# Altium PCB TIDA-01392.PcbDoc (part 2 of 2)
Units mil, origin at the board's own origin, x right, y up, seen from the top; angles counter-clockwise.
Board outline 1055.12 x 1877.5 mil, 6 copper layers (Layer 1 - Top Layer, Layer 2 - GND, Layer 3 - Signal, Layer 4 - Signal, Layer 5 - PWR, Layer 6 - Bottom Layer), stack 66.234 mil thick; 89 components, 55 nets, 288 pads, 112 vias.
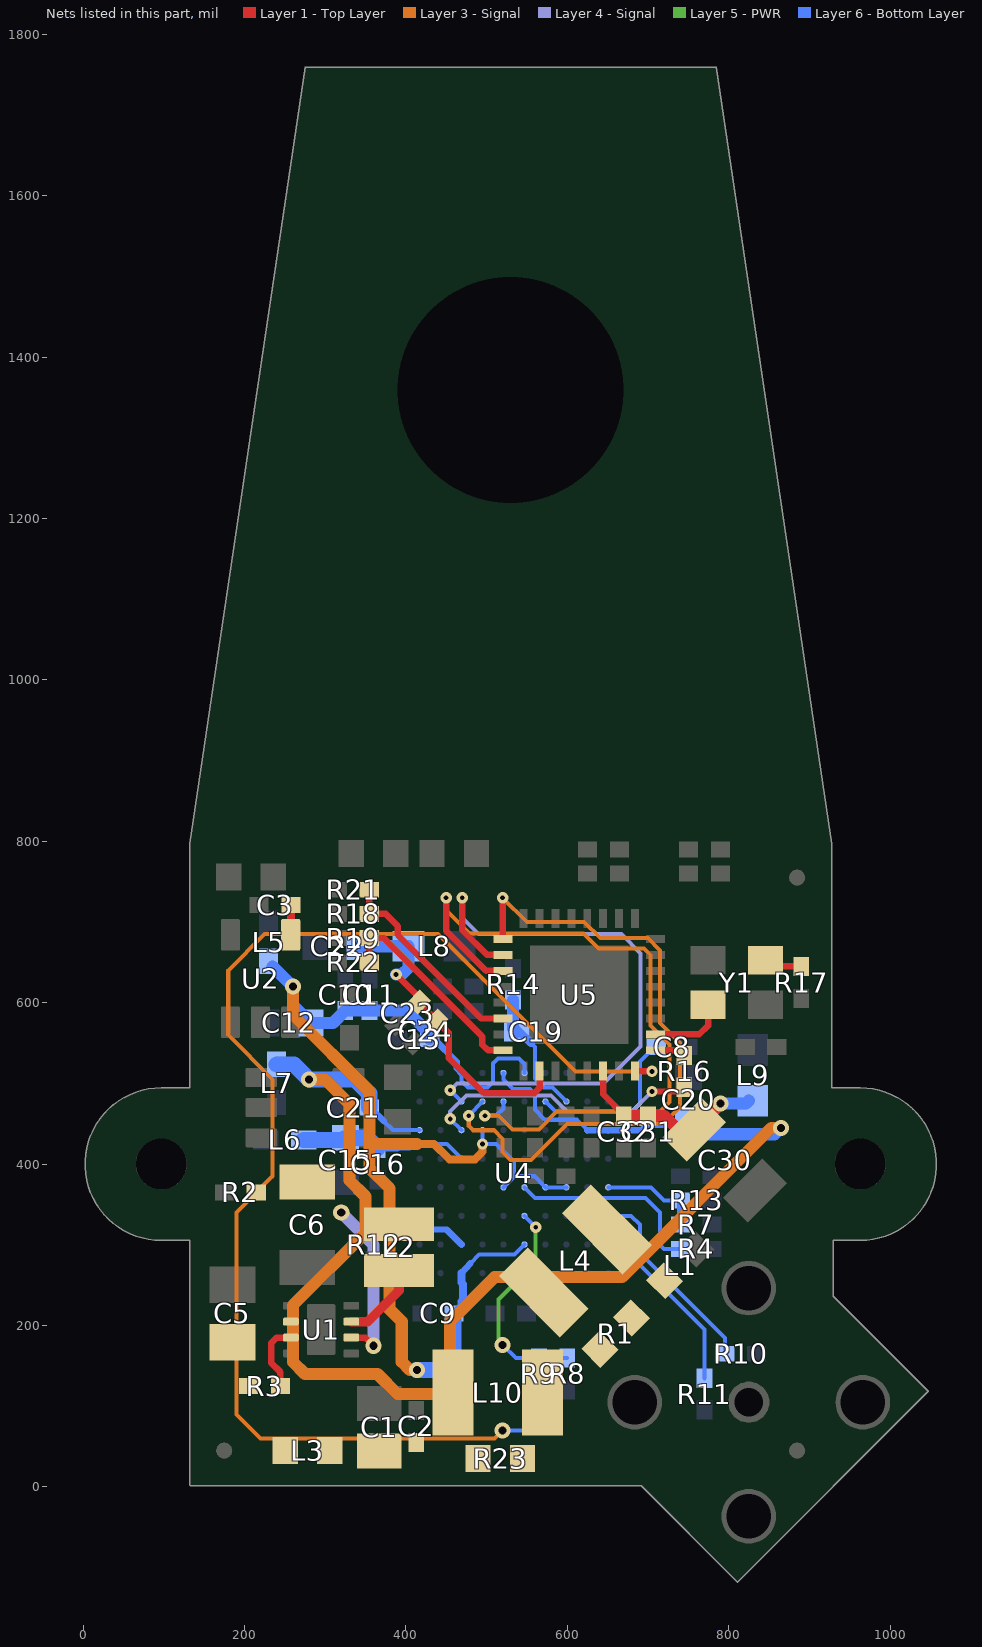
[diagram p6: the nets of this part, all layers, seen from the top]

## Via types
v1: diameter 20, hole 10, Layer 1 - Top Layer to Layer 6 - Bottom Layer, tented both sides, 57 vias
v2: diameter 14, hole 6, Layer 1 - Top Layer to Layer 6 - Bottom Layer, tented both sides, 46 vias
v3: diameter 19.68, hole 7.87, Layer 1 - Top Layer to Layer 6 - Bottom Layer, tented both sides, 7 vias
v4: diameter 20, hole 10, Layer 1 - Top Layer to Layer 6 - Bottom Layer, 2 vias

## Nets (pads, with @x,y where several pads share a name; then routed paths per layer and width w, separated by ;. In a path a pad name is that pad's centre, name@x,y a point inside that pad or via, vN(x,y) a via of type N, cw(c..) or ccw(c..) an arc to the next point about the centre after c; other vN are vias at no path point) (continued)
HSYNC: U4.B7 U5.1 | length 831.3
  Layer 1 - Top Layer w8: v2(520,730) 520,679.41 U5.1@520.51,678.9
  Layer 3 - Signal w5: v2(478,460) 478,447 483,442 509,442 520,431 520,415 530,405 555,405 600,450 719,450 740,471 740,550 715,575 715,665 700,680 641,680 621,700 550,700 v2(520,730)
  Layer 6 - Bottom Layer w5: v2(478,460) 478,460.56 U4.B7@495.02,477.58
NetC1_1: C1.1 C2.1 L3.1 L10.2 R23.1
NetC3_1: C3.1 U2.4 | length 37.4
  Layer 1 - Top Layer w10: U2.4@257.4,684.13 257.68,684.42 C3.1@257.68,719 ; C3.1@257.4,718.72 C3.1@257.68,719 ; C3.1@257.68,721 C3.1@257.68,719
NetC6_1: C6.1 L2.2 R2.2 U1.6 | length 213.6
  Layer 1 - Top Layer w8: U1.6@332.56,185 U1.6@332.4,185.16 349.84,185.16 v1(360,175)
  Layer 4 - Signal w15: v1(320,340) 360,300 v1(360,175)
NetC8_1: C8.1 U4.B4 | length 206.1
  Layer 6 - Bottom Layer w5: U4.B4@572.98,477.58 585.56,465 680,465 690,475 690,527 708,545 C8.1@710.32,545
NetC9_1: C9.1 C10.1 C11.1 C12.1 C13.1 L5.2 U4.A5 U4.A8 U4.C7 U4.E3 U4.E4 U4.E6 U4.G5 U4.H8 | length 1592.5
  Layer 3 - Signal w10: 414,425 435,425 454,406 485.57,406 495,415.43 v2(495,425)
  Layer 3 - Signal w15: v1(260,620) 260,585 355,490 355,425 ; v1(414,145) 405,145 395,155 395,205 380,220 380,370 355,395 355,425 ; 414,425 355,425
  Layer 6 - Bottom Layer w5: U4.A8@469.04,513.02 469.04,502.96 477,495 501,495 508,502 508,525 514,531 540,531 546.99,524.01 U4.A5@546.99,513.02 ; 480,277 491,288 534.57,288 U4.G5@546.99,300.42 ; U4.C7@495.02,442.15 v2@495.02,428 ; U4.E6@521.01,371.28 534,384.28 534,403 512,425 v2(495,425) ; 534.72,385 559.26,385 U4.E4@572.98,371.28 U4.E3@598.96,371.28 ; v2(495,425) v2@495,427.98 ; v2(495,425) v2@495.02,428
  Layer 6 - Bottom Layer w8: C13.1@429.68,555 435,555 463.04,526.96 463.04,519.02 U4.A8@469.04,513.02 ; U4.H8@469.04,264.98 480,277
  Layer 6 - Bottom Layer w10: C9.1@462,215 C9.1@459.68,215 469.04,224.35 469.04,229.9 471,231.86 471,251.14 469.04,253.1 U4.H8@469.04,264.98
  Layer 6 - Bottom Layer w15: L5.2@235,645 v1(260,620) 260,597.56 C12.1@282.56,575 309.68,575 C10.1@325,590.32 C11.1@355,590.32 400.68,590.32 432.84,558.16 C13.1@429.68,555
  Layer 6 - Bottom Layer w20: v1(414,145) 435,145 459,155 C9.1@459,210
NetC15_1: C15.1 C16.1 L6.2 U4.D8 | length 211.6
  Layer 6 - Bottom Layer w5: 389.68,419.68 404.68,419.68 410,425 450.76,425 U4.D8@469.04,406.72
  Layer 6 - Bottom Layer w8: C16.1@365,419.68 389.68,419.68
  Layer 6 - Bottom Layer w20: L6.2@273.62,430 322.44,430 C15.1@325,432.56 352.13,432.56 C16.1@365,419.68
NetC19_1: C19.1 R14.1 U4.B3 | length 161.4
  Layer 6 - Bottom Layer w5: 555,550 560,545 560,506 571,495 581.54,495 U4.B3@598.96,477.58
  Layer 6 - Bottom Layer w10: C19.1@537.38,564 541,564 555,550
  Layer 6 - Bottom Layer w15: R14.1@533,603.32 533,568.38 C19.1@537.38,564
NetC20_1: C20.1 C21.1 L7.2 U4.A6 U4.C1 U4.C2 U4.C10 | length 1852.9
  Layer 3 - Signal w15: v1(280,505) 300,505 330,475 330,380 350,360 350,315 260,225 260,155 275,140 365,140 390,115 440,115 455,130 455,205 510,260 668,260 853,445 v1(865,445)
  Layer 6 - Bottom Layer w5: 373,453 383.85,442.15 U4.C10@417.07,442.15 ; U4.A6@521.01,513.02 521.01,504.99 533,493 554,493 560,487 560,467.65 572.65,455 612.09,455 U4.C2@624.94,442.15
  Layer 6 - Bottom Layer w8: C21.1@354.68,470 356,470 373,453 ; U4.C2@624.94,442.15 U4.C1@650.93,442.15 692.15,442.15 698.5,448.5 C20.1@750,448.5
  Layer 6 - Bottom Layer w15: C20.1@750,452.44 765.44,437 857,437 v1(865,445)
  Layer 6 - Bottom Layer w20: L7.2@240,523.62 261.38,523.62 v1(280,505) 337,505 354.68,487.32 C21.1@354.68,470
NetC22_1: C22.1 C23.1 C24.1 L8.2 U5.10 | length 390.9
  Layer 1 - Top Layer w8: v2(388,635) 415.92,607.08 C23.1@415.92,600.92 415.92,599.92 C24.1@437.92,577.92 453,562.84 453,532 497,488 559,488 565.79,494.79 U5.10@565.79,515.51
  Layer 6 - Bottom Layer w15: C22.1@342.56,670 L8.2@403.5,670 403.5,643.5 395,635 v2(388,635)
NetC30_1: C30.1 C31.1 C32.1 L9.2 U5.14 | length 243.3
  Layer 1 - Top Layer w8: U5.14@644.53,515.51 644.53,486.47 670,461 C32.1@670,459.68
  Layer 1 - Top Layer w15: C32.1@670,459.68 C31.1@700,459.68 720.32,459.68 737.42,442.58 C30.1@757.42,442.58 v1(789.84,475)
  Layer 6 - Bottom Layer w15: v1(789.84,475) 821.5,475 L9.2@825,478.5
NetL1_1: L1.1 L4.1 R1.2
NetL2_1: L2.1 U1.7 | length 100.1
  Layer 1 - Top Layer w12: U1.7@332.4,204.84 352.84,204.84 391.5,243.5 L2.1@391.5,268.46
NetL4_2: L4.2 L10.1 R1.1 R23.2
NetR3_1: R3.1 U1.3 | length 85.4
  Layer 1 - Top Layer w8: R3.1@244.68,125 244.68,142.32 233,154 233,178 240.16,185.16 U1.3@257.6,185.16
NetR4_1: R4.1 U4.E5 | length 248.4
  Layer 6 - Bottom Layer w5: U4.E5@546.99,371.28 560.28,358 697,358 715,340 715,300 720,295 R4.1@740.32,295
NetR7_1: R7.1 R13.2 U4.E1 | length 126.1
  Layer 6 - Bottom Layer w5: U4.E1@650.93,371.28 703.72,371.28 720,355 R13.2@740.31,355
  Layer 6 - Bottom Layer w8: R7.1@740.32,325 R13.2@740.31,355
NetR8_1: R8.1 R9.1 U4.F5 | length 272.6
  Layer 5 - PWR w5: v1(520,176) 515,185 515,232.02 560.98,278 v2(560.98,321.86)
  Layer 6 - Bottom Layer w5: v1(520,176) 536.68,159.68 R9.1@565,159.68 R8.1@600,159.68 ; U4.F5@546.99,335.85 v2(560.98,321.86)
NetR10_2: R10.2 U4.F1 | length 247.2
  Layer 6 - Bottom Layer w5: U4.F1@650.93,335.85 679.15,335.85 690,325 690,290 795.31,184.69 R10.2@795.31,165
NetR11_2: R11.2 U4.F2 | length 281.3
  Layer 6 - Bottom Layer w5: U4.F2@624.94,335.85 636.8,324 671,324 680,315 680,285 770,195 R11.2@770,134.69
NetR12_2: R12.2 U4.G8 | length 117
  Layer 6 - Bottom Layer w8: R12.2@360,319.69 360.69,319 450.46,319 U4.G8@469.04,300.42
NetR16_1: R16.1 U5.17 | length 38.2
  Layer 1 - Top Layer w8: U5.17@709.49,541.1 738.58,541.1 R16.1@745,534.68
NetR17_1: R17.1 Y1.1 | length 47.8
  Layer 1 - Top Layer w8: Y1.1@845.43,652.56 852.99,645 889.68,645 R17.1@890,644.68
NetR18_1: R18.1 R21.2 U5.6 | length 255.9
  Layer 1 - Top Layer w8: R21.2@354.69,740 R18.1@354.68,710 375,710 390,695 390,684 493.53,580.47 U5.6@520.51,580.47
NetR19_1: R19.1 R22.2 U5.8 | length 259.2
  Layer 1 - Top Layer w8: R22.2@354.69,650 R19.1@354.68,680 373,680 494.9,558.1 494.9,548.1 501.9,541.1 U5.8@520.51,541.1
NetU5_18: U5.18 Y1.3 | length 95.4
  Layer 1 - Top Layer w8: U5.18@709.49,560.79 763.79,560.79 774.57,571.57 Y1.3@774.57,597.44
NRST: R9.2 U5.16 | length 1662.8
  Layer 1 - Top Layer w8: U5.16@683.9,515.51 684.41,515 v2(705,515)
  Layer 3 - Signal w5: v1(520,70) 510,60 220,60 190,90 190,340 235,385 235,505 180,560 180,640 225,685 440,685 610,515 v2(705,515)
  Layer 6 - Bottom Layer w5: v1(520,70) 536,70 555,70 565,80 R9.2@565,120.31
PCLK: U4.B6 U5.3 | length 900.6
  Layer 1 - Top Layer w8: v2(450,730) 450,689 499.47,639.53 U5.3@520.51,639.53
  Layer 3 - Signal w5: v2(450,730) 450,715 479,686 620,686 639,667 695,667 703,659 703,572 727,548 727,477 715,465 587,465 565,443 532,443 515,460 v2(498,460)
  Layer 6 - Bottom Layer w5: v2(498,460) 512,460 521.01,469.01 U4.B6@521.01,477.58
VCC_POC: C5.1 L3.2 R3.2 U1.2
VSYNC: U4.B8 U5.2 | length 760.8
  Layer 1 - Top Layer w8: v2(470,730) 470,690 500.79,659.21 U5.2@520.51,659.21
  Layer 4 - Signal w5: v2(455.05,491.57) 463.47,500 645,500 691,546 691,661 667,685 490,685 470,705 v2(470,730)
  Layer 6 - Bottom Layer w5: v2(455.05,491.57) U4.B8@469.04,477.58
XCLK: R16.2 U4.C8 | length 347.8
  Layer 1 - Top Layer w8: v2(705,490) 739.69,490 R16.2@745,495.31
  Layer 4 - Signal w5: v2(455.05,456.14) 455.05,465.05 475,485 580,485 600,465 680,465 v2(705,490)
  Layer 6 - Bottom Layer w5: v2(455.05,456.14) U4.C8@469.04,442.15
pads on no net: FID1.1 FID2.1 FID3.1 FID4.1 FID5.1 FID6.1 LH1.MT1 LH1.MT2 U3.4 U4.C5

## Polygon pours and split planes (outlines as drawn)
1V8 on Layer 5 - PWR "Layer 5 - PWR- 1V8" (solid, remove dead copper, pour order 2): 295,792 605.5,792 613.5,784 613.5,758.5 605,750 511,750 502,741 502,722 512.97,711.03 676.03,711.03 712,747 712,787 717,792 744,792 801,735 898,735 898,408 830,340 830,305 820,295 785,295 624.75,134.75 624.75,49.75 606,31 163,31 163,389 199,425 199,484 163,520 163,759.5 262.5,759.5
GND on Layer 2 - GND "Layer 2 - GND- GND" (solid, remove dead copper, pour order 4): 0,-120 1060,-120 1060,802 0,802

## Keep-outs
Keep-Out Layer:
  lines w10: 96.88,300.51 ccw(c96.93,400) 96.93,300.51 ; 96.88,300.51 cw(c96.93,400) 96.88,499.49 ; 96.88,300.51 ccw(c96.93,305.51) 96.93,300.51 ; 96.88,499.49 cw(c96.93,494.49) 96.93,499.49 ; 96.88,499.49 cw(c96.93,494.49) 96.93,499.49 ; 96.88,499.49 cw(c96.93,400) 96.93,499.49 ; 96.93,300.51 127.36,300.51 127.36,2.36 ; 96.93,499.49 127.36,499.49 127.36,796.93 ; 127.36,2.36 ccw(c132.36,2.36) 128.84,-1.19 ; 127.36,2.36 ccw(c132.36,2.36) 128.83,-1.17 128.84,-1.19 ; 127.36,796.93 cw(c132.36,797) 127.36,797 ; 127.36,796.93 cw(c132.36,797) 127.36,797 ; 127.36,796.93 127.36,797.07 ; 127.36,797 cw(c132.36,797) 127.36,797.07 ; 127.36,797 127.36,797.64 ; 127.36,797.07 127.36,797.64 ; 127.36,797.64 cw(c132.36,797.64) 127.65,799.31 ; 127.36,797.64 ccw(c132.36,797.64) 127.36,797.64 ; 127.36,797.64 cw(c132.36,797.64) 127.65,799.31 ; 127.65,799.31 270.3,1760.23 ; 128.84,-1.19 129.8,-2.15 ; 129.82,-2.17 ccw(c133.35,1.37) 133.35,-3.63 ; 129.8,-2.15 ccw(c133.35,1.37) 133.35,-3.63 ; 129.8,-2.15 129.82,-2.17 ; 133.35,-3.63 689.56,-3.63 807.45,-121.52 ; 270.3,1760.23 cw(c275.25,1759.5) 275.25,1764.5 ; 270.3,1760.23 cw(c275.25,1759.5) 275.25,1764.5 ; 275.25,1764.5 784.75,1764.5 ; 784.75,1764.5 cw(c784.75,1759.5) 789.7,1760.23 ; 784.75,1764.5 cw(c784.75,1759.5) 789.7,1760.23 ; 789.7,1760.23 932.35,799.31 ; 807.45,-121.52 ccw(c811,-118) 814.54,-121.54 814.55,-121.52 ; 807.45,-121.52 807.46,-121.54 ccw(c811,-118) 814.55,-121.52 ; 814.55,-121.52 1051.02,114.95 ; 932.35,799.31 cw(c927.64,797.64) 932.64,797.64 ; 932.35,799.31 cw(c927.64,797.64) 932.64,797.64 ; 932.64,796.91 ccw(c927.64,797) 932.64,797 ; 932.64,796.91 ccw(c927.64,797) 932.64,797 ; 932.64,796.91 932.64,797.09 ; 932.64,796.91 932.64,499.49 963.07,499.49 ; 932.64,797.01 ccw(c927.64,797) 932.64,797.09 ; 932.64,797 ccw(c927.64,797) 932.64,797.01 ; 932.64,797 ccw(c927.64,797) 932.64,797.01 ; 932.64,797.01 932.64,797.64 ; 932.64,797.09 932.64,797.64 ; 932.64,797.64 ccw(c927.64,797.64) 932.64,797.64 ; 963.07,300.51 ccw(c963.07,400) 963.12,300.51 ; 963.07,300.51 ccw(c963.07,305.51) 963.12,300.51 ; 963.07,300.51 ccw(c963.07,305.51) 963.12,300.51 ; 963.07,300.51 ccw(c963.07,305.51) 963.07,300.51 ; 963.07,300.51 934.63,300.51 934.63,238.44 1051.02,122.05 ; 963.07,499.49 cw(c963.07,494.49) 963.12,499.49 ; 963.07,499.49 cw(c963.07,400) 963.12,499.49 ; 963.07,499.49 ccw(c963.07,494.49) 963.07,499.49 ; 963.07,499.49 cw(c963.07,494.49) 963.12,499.49 ; 963.12,300.51 ccw(c963.07,400) 1062.56,400 ccw(c963.07,400) 963.12,499.49 ; 1051.02,114.95 ccw(c1047.5,118.5) 1052.5,118.5 ; 1051.02,114.95 1051.04,114.96 ccw(c1047.5,118.5) 1052.5,118.5 ; 1051.02,122.05 cw(c1047.5,118.5) 1052.5,118.5 ; 1051.02,122.05 1051.04,122.04 cw(c1047.5,118.5) 1052.5,118.5
  text ".Layer_Name" at 577,-858.49 h60

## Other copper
Layer 1 - Top Layer:
  region net NetL4_2: 551,297 627,221 627,208 664,171 640,147 595,102 595,64 560,29 560,17 530,17 529,18 529,53 542,66 542,171 552,171 576.75,195.75 513.25,259.25
  region net NetC1_1: 288,65 290,67 425,67 433,75 433,172 485,172 486,171 485,170 485,63.32 495.32,53 506,53 506,19 507,18 506,17 288,17
  region net 1V8: 309,491 407,491 407,523 355,575 309,575
  region net 1V5: 160,660 160,795 205,795 205,746 195,731 195,712 195,681 195,660
  region net GND: 550,419 550,433 570,433 570,419
  region net GND: 790,360 825,325 865,325 895,355 840,410
  region net 3V3: 188,355 188,398 210,420 241,420 241,445 195,445 190,450 190,490 195,495 241,495 270,524 270,596 245,596 245,550 240,545 200,545 195,550 195,596 160,596 160,355
  region net DOUT_N: 590,419 590,433 610,433 610,419
  region net DOUT_P: 620,419 620,433 640,433 640,419
  region net GND: 660,433 710,433 710,405 690,385 680,385 660,405
  region net 1V8: 820,620 900,620 900,542 893,535 865,535 845,535 845,555 820,580
  region net 1V8: 763,750 753,740 747,740 737,750 715,750 715,800 763,800
  region net GND: 777,750 825,750 825,800 777,800
  region net GND: 652,750 700,750 700,800 652,800
  region net 1V8: 638,750 628,740 622,740 612,750 590,750 590,800 638,800
  region net NetC6_1: 435,297 348,297 310,335 200,335 200,390 210,400 326,400 364,362 435,362
  region net GND: 425,125.5 425,81 293,81 270,104 270,138 247,161 247,171 270,171 277,178 277,212 270,219 155,219 155,320.5 294.5,320.5 313,302 313,133 320.5,125.5 335,125.5 350,125.5 375,125.5 400.5,125.5 415.5,125.5 420.5,125.5
  region net VCC_POC: 268,22 268,82 245,105 225,105 218,112 218,191 227,200 268,200 268,210 155,210 155,120 215,60 215,40 233,22
  region net NetL1_1: 643.5,361.5 745,260 745,251 680,186 654.5,211.5 638.18,291.18 606.25,324.25
  text ".Layer_Name" at 577,-858.49 h60
Layer 2 - GND:
  pour cut-out: 912.25,521.63 867.61,521.63 867.61,595.39 912.25,595.39
  pour cut-out: 459.08,297.08 459.08,325 437.71,325 437.71,370 385.75,370 385.75,415 437.71,415 437.71,508.91 480,508.91 480,479.33 558.33,479.33 558.33,444.67 517,444.67 517,409 532.33,409 532.33,367.18 552.33,367.18 552.33,297.08
  pour cut-out: 147.75,764.7 229.7,764.7 230,765 230,802 277,802 277,761 323,761 323,810 156,810 147.75,801.75
  pour cut-out: 502,712 502,803 677,803 680,800 680,712
  pour cut-out: 702,804 702,739 749,739 749,804
  text ".Layer_Name" at 577,-858.49 h60
Layer 5 - PWR:
  pour cut-out: 484,295 439,340 439,366 430,375 395,375 385,385 385,402 411,428 411,536 420,545 436,545 447,534 447,525 494,478 512,478 559,431 559,313 541,295
  text ".Layer_Name" at 577,-858.49 h60
Layer 3 - Signal:
  text ".Layer_Name" at 577,-858.49 h60
Layer 4 - Signal:
  text ".Layer_Name" at 577,-858.49 h60
Layer 6 - Bottom Layer:
  region net GND: 447,438 437,438 378,497 378,535 378,565 403,565 403,543 411,535 434,535 447,522 447,511 438,502 438,489 447,480 447,475 438,466 438,453 447,444
  region net GND: 613,473 655,473 655,515 675,535 675,670 555,670 554,669 554,590 569,575 569,510 572,507 590,507 613,484
  region net GND: 421,331 421,373 417,377 390,377 385,382 385,390 380,395 250,395 220,365 220,299 294,299 300,305 300,353 308,361 333,361 349,345 372,345 386,331
  region net 1V8: 767,335 810,335 825,320 825,300 810,285 767,285
  region net GND: 621,305 653,305 657,301 657,263 725,195 725,80 710,65 665,65 645,85 645,226 626,245 602,245 595,252 595,279
  region net GND: 565,269 577,269 577,255 565,243 565,195 550,180 540,180 535,185 535,260 544,269
  region net GND: 445,305 458.5,291.5 458.5,249.5 461,243 460,236.37 457,232 453,230 450,230 445,230 437,229 432,224 432,221.86 432,205 399.07,205 399.07,296.07 408,305
  text ".Layer_Name" at 577,-858.49 h60

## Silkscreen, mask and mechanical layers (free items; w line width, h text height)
Top Overlay:
  lines w7: 380,750 425,750 ; 520,385 520,395 ; 790,480 825,480
  text ".Layer_Name" at 577,-858.49 h60
Bottom Overlay:
  lines w10: 195,65 865,65 865,735 195,735 195,65
  text "TIDA-01392" at 205,1191 h70 r180
  text "ADAS-CAM-EVM-01392" at 179,906 h70 r180
  text ".Layer_Name" at 577,-858.49 h60
Top Paste:
  text ".Layer_Name" at 577,-858.49 h60
Bottom Paste:
  text ".Layer_Name" at 577,-858.49 h60
Top Solder:
  text ".Layer_Name" at 577,-858.49 h60
  text ".Layer_Name" at 577,-858.49 h60
Bottom Solder:
  text ".Layer_Name" at 577,-858.49 h60
Drill Guide:
  text ".Layer_Name" at 577,-858.49 h60
M1 Board Outline:
  lines w10: 132.36,2.36 132.36,305.51 96.93,305.51 cw(c96.93,400) 96.93,494.49 132.36,494.49 132.36,797.64 ; 132.36,797 275.25,1759.5 784.75,1759.5 927.64,797 ; 133.35,1.37 691.63,1.37 811,-118 1047.5,118.5 929.63,236.37 929.63,305.51 963.07,305.51 ccw(c963.07,400) 963.07,494.49 927.64,494.49 927.64,797.64 ; 137,822 164,822 ; 196,822 227.64,822 ; 259.64,822 291.28,822 ; 323.28,822 354.91,822 ; 386.91,822 418.55,822 ; 450.55,822 482.19,822 ; 514.19,822 545.83,822 ; 520,783 537,783 ; 530,735 530,775 ; 577.83,822 609.46,822 ; 641.46,822 673.1,822 ; 705.1,822 736.74,822 ; 768.74,822 800.38,822 ; 832.38,822 864.02,822 ; 896.02,822 922.97,822 ; 510,775 530,795 550,775 510,775
  text "V-SCORE" at 370,666 h75
  text ".Layer_Name" at 577,-858.49 h60
M2 Board Dimensions:
  rectangle: -0.5,-285.5 124.5,-160.5
  rectangle: 124.5,-410.5 499.5,-285.5
  lines w7: -0.5,-285.5 999.5,-285.5 ; 124.5,-410.5 124.5,-160.5 ; 249.5,-410.5 249.5,-160.5 ; 499.5,-410.5 499.5,-160.5 ; 749.5,-410.5 749.5,-160.5 ; -0.5,-410.5 999.5,-410.5 999.5,-160.5 -0.5,-160.5 -0.5,-410.5
  lines w10: -40,400 530,400 ; -0.5,-475.5 -0.5,-455.5 ; 59.5,-485.5 -0.5,-465.5 ; 59.5,-445.5 -0.5,-465.5 ; 223.58,-465.5 -0.5,-465.5 ; 530,-170 530,400 ; 530,970 530,400 ; 775.42,-465.5 999.5,-465.5 ; 939.5,-485.5 999.5,-465.5 ; 939.5,-445.5 999.5,-465.5 ; 999.5,-475.5 999.5,-455.5 ; 1100,400 530,400
  text "1000 (mil)" at 233.58,-501.49 h60
  text ".Layer_Name" at 577,-858.49 h60
M3 3D STEP Top:
  text ".Layer_Name" at 577,-858.49 h60
M4 3D STEP Bottom:
  text ".Layer_Name" at 577,-858.49 h60
M5 Assembly Top:
  lines w10: -292,-930.17 6308,-930.17 ; -292,-726.83 6310,-726.83 ; -292,-523.5 -292,-1133.5 3713,-1133.5 6310,-1133.5 6310,-523.5 -291.5,-523.5 -291.5,-1133.5 1284,-1133.5 ; 2173,-1133.5 2173,-523.5 ; 3440,-726.83 3440,-523.5 ; 4280,-726.83 4280,-523.5 ; 4902,-1140 4902,-937.17
  text "COMPONENTS MARKED 'DNP' SHOULD NOT BE POPULATED." at 1153.5,-318.5 h60
  text "ASSEMBLY VARIANT:" at 1153,-434 h60
  text ".VariantName" at 2189,-434 h60
  text "PCB VIEWED FROM TOP SIDE" at -228.5,-655.67 h60
  text "BOARD #:" at 2248,-655.67 h60
  text ".PRJ_Number" at 2793.5,-655.67 h60
  text "REV:" at 3638,-655.67 h60
  text ".PCB_Rev" at 3929.5,-655.67 h60
  text "SVN REV:" at 4476,-655.67 h60
  text ".VersionControl_RevNumber" at 4982,-655.67 h60
  text "IGNORE ->" at -228.5,-858.49 h60
  text "PLOT NAME =" at -228.5,-1064.34 h60
  text ".plot_File_Name" at 577,-1064.34 h60
  text "GENERATED    :" at 2250,-1064.34 h60
  text ".Print_Date" at 3119.5,-1064.34 h60
  text ".Print_Time" at 3848.5,-1064.34 h60
  text "TEXAS INSTRUMENTS" at 5113,-1064.34 h60
M6 Assembly Bottom:
  lines w10: -292.5,-727.33 6309.5,-727.33 ; -290.5,-930.67 6309.5,-930.67 ; 1115.5,-1140.5 1115.5,-937.67 ; 1737.5,-727.33 1737.5,-524 ; 2577.5,-727.33 2577.5,-524 ; 3844.5,-1134 3844.5,-524 ; 4733.5,-1134 6309,-1134 6309,-524 -292.5,-524 -292.5,-1134 2304.5,-1134 6309.5,-1134 6309.5,-524
  text "COMPONENTS MARKED 'DNP' SHOULD NOT BE POPULATED." at 6102,-318 h60
  text ".VariantName" at 5058,-434 h60
  text "ASSEMBLY VARIANT:" at 6097,-434 h60
  text ".VersionControl_RevNumber" at 1035.5,-656.17 h60
  text "SVN REV:" at 1541.5,-656.17 h60
  text ".PCB_Rev" at 2088,-656.17 h60
  text "REV:" at 2379.5,-656.17 h60
  text ".PRJ_Number" at 3224,-656.17 h60
  text "BOARD #:" at 3769.5,-656.17 h60
  text "PCB VIEWED FROM BOTTOM SIDE" at 6246,-656.17 h60
  text "IGNORE ->" at 2547.85,-858.49 h60
  text "TEXAS INSTRUMENTS" at 904.5,-1064.84 h60
  text ".Print_Time" at 2169,-1064.84 h60
  text ".Print_Date" at 2898,-1064.84 h60
  text "GENERATED    :" at 3767.5,-1064.84 h60
  text ".plot_File_Name" at 5440.5,-1064.84 h60
  text "PLOT NAME =" at 6246,-1064.84 h60
M9 Title Sheet:
  drawing of 1178 lines, arcs and shapes, not listed
  text "1" at 739.84,8036.5 h70
  text "2" at 3235.5,8036.5 h70
  text "3" at 5724.84,8036.5 h70
  text "4" at 8231.51,8036.5 h70
  text "5" at 10730.5,8036.5 h70
  text "6" at 13235.5,8036.5 h70
  text "A" at -416.5,6893.5 h70
  text "A" at 14383.5,6893.5 h70
  text "B" at -416.5,4513.5 h70
  text "B" at 14383.5,4513.5 h70
  text "C" at -416.5,2138.5 h70
  text "C" at 14383.5,2138.5 h70
  text "PROJECT TITLE:" at 11343.5,277.5 h45
  text ".PRJ_Title" at 11393.5,144.17 h70
  text "DESIGNED FOR:" at 11343.5,-23.5 h45
  text ".PRJ_Customer" at 11393.5,-163.5 h70
  text "D" at -416.5,-231.5 h70
  text "D" at 14383.5,-231.5 h70
  text "FILE NAME:" at 11343.5,-323.5 h45
  text ".PCB_File_Name_No_Path" at 11393.5,-443.5 h70
  text "Texas Instruments (TI) and/or its licensors do not warrant the accuracy or completeness of this specification" at 6374,-605.34 h45
  text "ENGINEER:" at 11343.5,-613.5 h45
  text "LAYOUT BY:" at 12848.5,-613.5 h45
  text "or any information contained therein. TI and/or its licensors do not warrant that this design will meet" at 6329.01,-718 h45
  text ".PRJ_Engineer" at 11393.5,-768.49 h70
  text "JMM" at 12852,-800 h100
  text "s  o  l  u  t  i  o  n  s" at 13710,-803 h68
  text "the specifications, will be suitable for your application or fit for any particular purpose, or will operate in" at 6329.01,-830.67 h45
  text ".Layer_Name" at 577,-858.49 h60
  text "ALTIUM DESIGNER VERSION:" at 12848.5,-923.5 h45
  text "an implementation. TI and/or its licensors do not warrant that the design is production worthy. You should" at 6329.01,-943.33 h45
  text "completely validate and test your design implementation to confirm the system functionality for your application." at 6374,-1056 h45
  text ".print_Scale" at 11393.5,-1056.83 h70
  text ".Application_BuildNumber" at 12899,-1056.83 h70
  text "1" at 739.84,-1263.5 h70
  text "2" at 3235.5,-1263.5 h70
  text "3" at 5724.84,-1263.5 h70
  text "4" at 8231.51,-1263.5 h70
  text "5" at 10730.5,-1263.5 h70
  text "6" at 13235.5,-1263.5 h70
M10 Fab Notes:
  drawing of 212 lines, arcs and shapes, not listed
  text "DESIGN INFORMATION" at 12381.02,6810 h60
  text "(REFER ALSO ARRAY/PANEL PROFILING INFORMATION)" at 12019.46,6648.29 h60
  text "BOARD SIZE" at 11333.46,6644 h60
  text "795.28MIL" at 11795.78,6516.18 h60
  text "X" at 12301.46,6516.18 h60
  text "795.28MIL" at 12532.78,6516.18 h60
  text "Number of Layers :" at 11736.46,6319 h60
  text "6" at 12831.27,6309 h60
  text "MIN. TRACK WIDTH:" at 11736.46,6180 h60
  text "5" at 12832.7,6180 h60
  text "MIL" at 12987.46,6180 h60
  text "MIN. CLEARANCE:" at 11736.46,6048 h60
  text "5" at 12832.7,6048 h60
  text "MIL" at 12987.46,6048 h60
  text "MIN. VIA PAD SIZE:" at 11736.46,5916 h60
  text "14" at 12802.71,5916 h60
  text "MIL" at 12987.46,5916 h60
  text "0.05mm (2MIL)" at 12431.46,5774.29 h60
  text "MINIMUM ANNULAR RING" at 11407.23,5770 h60
  text "EXTERNAL" at 13139.46,5770 h60
  text "PER" at 11607.23,5652 h60
  text "IPC-D-275 CLASS 2 LEVEL C" at 11827.23,5652 h60
  text "MIL, HOLES" at 13315.46,5539.71 h60
  text "+/-" at 12923,5539 h60
  text "+/-" at 13777,5539 h60
  text "REGISTRATION TOLERANCES:" at 11407.23,5534 h60
  text "METAL" at 12607,5534 h60
  text "5" at 13183.2,5534 h60
  text "3" at 14016.2,5534 h60
  text "MIL" at 14132.46,5534 h60
  text "MATERIAL:" at 11332.46,5324.54 h60
  text "FR-4 High Tg" at 12318.9,5184.21 h60
  text "FR-408" at 11753.46,5175.64 h60
  text "X" at 12165.46,5175.64 h60
  text "OTHER" at 13241.46,5175.64 h60
  text "62 MIL (1.6mm) +/-10%" at 12073.56,5012.92 h60
  text "THICKNESS:" at 11407.23,5008.64 h60
  text "X" at 11945.4,5008.64 h60
  text "OTHER" at 13358.46,5008.64 h60
  text "TOLERANCE:" at 11407.23,4850.64 h60
  text "X" at 12246.53,4850.64 h60
  text "ANSI IPC-6012 TYPE 3 CLASS 2" at 12433.48,4850.64 h60
  text "OTHER +/-" at 12433.46,4694.64 h60
  text "BOW & TWIST:" at 11407.23,4537.64 h60
  text "X" at 12246.53,4537.64 h60
  text "ANSI IPC-6012 TYPE 3 CLASS 2" at 12433.48,4537.64 h60
  text "OTHER +/-" at 12433.46,4379.13 h60
  text "COPPER THICKNESS (FINISHED):" at 11332.46,4243.64 h60
  text "1.4MIL (1oz)" at 12212.46,4090.92 h60
  text "2MIL (1.4oz)" at 12979.46,4090.92 h60
  text "2.8MIL (2oz)" at 13706.46,4090.92 h60
  text "OUTER:" at 11689.46,4086.64 h60
  text "X" at 12084,4086 h60
  text "1.4MIL (1oz)" at 12212.46,3933.92 h60
  text "2.8MIL (2oz)" at 12979.46,3933.92 h60
  text "N/A" at 13706,3934.29 h60
  text "INNER SIGNAL:" at 11400.38,3929.64 h60
  text "X" at 12085.42,3929.64 h60
  text "DRILLING:" at 11332.46,3790.64 h60
  text "REFERENCE:" at 11407.23,3673.64 h60
  text "X" at 12055.46,3673.64 h60
  text "AS SHOWN" at 12242.46,3673.64 h60
  text "X" at 12956.46,3673.64 h60
  text "NC_DRILL FILES" at 13093.46,3673.64 h60
  text "PTH MIN COPPER THICKNESS:" at 11407.23,3515.64 h60
  text "X" at 12757.46,3515.64 h60
  text "1MIL" at 12894.46,3515.64 h60
  text "OTHER" at 13391.46,3515.64 h60
  text "BOARD FINISH:" at 11332.46,3356.64 h60
  text "SILKSCREEN:" at 11487.68,3238.64 h60
  text "X" at 12436.46,3238.64 h60
  text "TOP" at 12562.46,3238.64 h60
  text "X" at 12946.46,3238.64 h60
  text "BOTTOM" at 13073.46,3238.64 h60
  text "SILKSCREEN COLOR:" at 11487.68,3071.64 h60
  text "X" at 12435.42,3071.64 h60
  text "WHITE" at 12562.46,3071.64 h60
  text "OTHER" at 13073.46,3071.64 h60
  text "SOLDER RESIST COLOR:" at 11487.68,2901.64 h60
  text "GREEN" at 12182.46,2742.44 h60
  text "BLUE" at 12773.46,2742.44 h60
  text "OTHER" at 13311.46,2742.44 h60
  text "BLACK" at 13793.46,2742.44 h60
  text "X" at 13160,2740 h60
  text "IMMERSION GOLD (ENIG)" at 12393.46,2553.92 h60
  text "ENEPIG" at 13731,2550.64 h60
  text "SURFACE FINISH:" at 11332.46,2549.64 h60
  text "X" at 12206.51,2549.64 h60
  text "IMM. TIN/SILVER OR EQUIV" at 11662,2392.64 h60
  text "OTHER" at 13093.46,2392.64 h60
  text "ARRAY/PANEL:" at 11332.46,2213.64 h60
  text "CUT AND TRIM PER MECH LAYER 1" at 12393.46,2209.35 h60
  text "N.C. ROUTE" at 12393.46,2057.64 h60
  text "X" at 13072.46,2057.64 h60
  text "V. SCORE" at 13259.46,2057.64 h60
  text "CERTIFICATION:" at 11332.46,1920.64 h60
  text "MATERIALS AND WORKMANSHIP FOR ALL PCBS" at 12057.46,1920.64 h60
  text "TO MEET OR EXCEED THE REQUIREMENTS OF:" at 12057.46,1822.64 h60
  text "X" at 11683.96,1686.13 h60
  text "ANSI IPC-A-600F CLASS ->" at 11822.96,1686.13 h60
  text "X" at 13462.02,1686.13 h60
  text "2" at 13580.96,1686.14 h60
  text "1" at 13265.96,1684.64 h60
  text "3" at 13934.96,1684.64 h60
  text "X" at 11686.02,1526.64 h60
  text "UL 94V-0" at 11822.96,1526.64 h60
  text "X" at 12498.02,1526.64 h60
  text "RoHS" at 12634.96,1526.64 h60
  text "OTHER" at 13279.36,1526.64 h60
  text "PER ORDER" at 13676.42,1526.64 h60
  text "ADDITIONAL REQUIREMENTS:" at 11332.46,1385.64 h60
  text "MICROSECTION:" at 11407.23,1270.64 h60
  text "YES" at 12312.96,1270.64 h60
  text "REQUIRED" at 13174.46,1114.49 h60
  text "BARE BOARD ELEC. TEST:" at 11407.23,1111.64 h60
  text "NONE" at 12712.96,1111.64 h60
  text "X" at 13047.46,1111.64 h60
  text "PER ORDER" at 13766.46,1111.64 h60
  text "MANUFACTURER'S UL:" at 11407.23,954.64 h60
  text "RAIL" at 12572.96,950.35 h60
  text "METAL" at 13064.77,950.35 h60
  text "X" at 13440,950 h60
  text "SILK" at 13576.46,950.35 h60
  text ".Layer_Name" at 577,-858.49 h60
M11 Gerber Information:
  lines w10: -292,-930.17 6308,-930.17 ; -292,-726.83 6310,-726.83 ; -292,-523.5 -292,-1133.5 3713,-1133.5 6310,-1133.5 6310,-523.5 -291.5,-523.5 -291.5,-1133.5 1284,-1133.5 ; 2173,-1133.5 2173,-523.5 ; 3440,-726.83 3440,-523.5 ; 4280,-726.83 4280,-523.5 ; 4902,-1140 4902,-937.17
  text "ALL ARTWORK VIEWED FROM TOP SIDE" at -228.5,-655.67 h60
  text "BOARD #:" at 2248,-655.67 h60
  text ".PRJ_Number" at 2793.5,-655.67 h60
  text "REV:" at 3638,-655.67 h60
  text ".PCB_Rev" at 3929.5,-655.67 h60
  text "SVN REV:" at 4476,-655.67 h60
  text ".VersionControl_RevNumber" at 4982,-655.67 h60
  text "LAYER NAME =" at -228.5,-858.49 h60
  text "PLOT NAME =" at -228.5,-1064.34 h60
  text ".plot_File_Name" at 577,-1064.34 h60
  text "GENERATED    :" at 2250,-1064.34 h60
  text ".Print_Date" at 3119.5,-1064.34 h60
  text ".Print_Time" at 3848.5,-1064.34 h60
  text "TEXAS INSTRUMENTS" at 5113,-1064.34 h60
M12 Stackup:
  drawing of 399 lines, arcs and shapes, not listed
  text "Layer" at 6311,7843 h60
  text "Name" at 6720.91,7843 h60
  text "Material" at 8130.5,7843 h60
  text "Thickness" at 8990.27,7843 h60
  text "Constant" at 9640.1,7843 h60
  text "Board Layer Stack" at 10209.97,7843 h60
  text "1" at 6311,7723 h60
  text "Top Overlay" at 6720.91,7723 h60
  text "2" at 6311,7603 h60
  text "Top Solder" at 6720.91,7603 h60
  text "Solder Resist" at 8130.5,7603 h60
  text "0.40mil" at 8990.27,7603 h60
  text "3.5" at 9640.1,7603 h60
  text "3" at 6311,7483 h60
  text "Layer 1 - Top Layer" at 6720.91,7483 h60
  text "Copper" at 8130.5,7483 h60
  text "1.40mil" at 8990.27,7483 h60
  text "4" at 6311,7363 h60
  text "Dielectric 1" at 6720.91,7363 h60
  text "370HR" at 8130.5,7363 h60
  text "12.60mil" at 8990.27,7363 h60
  text "4.2" at 9640.1,7363 h60
  text "5" at 6311,7243 h60
  text "Layer 2 - GND" at 6720.91,7243 h60
  text "Copper" at 8130.5,7243 h60
  text "1.40mil" at 8990.27,7243 h60
  text "6" at 6311,7123 h60
  text "Dielectric 2" at 6720.91,7123 h60
  text "370HR" at 8130.5,7123 h60
  text "8.00mil" at 8990.27,7123 h60
  text "4.2" at 9640.1,7123 h60
  text "7" at 6311,7003 h60
  text "Layer 3 - Signal" at 6720.91,7003 h60
  text "Copper" at 8130.5,7003 h60
  text "1.42mil" at 8990.27,7003 h60
  text "8" at 6311,6883 h60
  text "Dielectric 3" at 6720.91,6883 h60
  text "370HR" at 8130.5,6883 h60
  text "16.60mil" at 8990.27,6883 h60
  text "4.2" at 9640.1,6883 h60
  text "9" at 6311,6763 h60
  text "Layer 4 - Signal" at 6720.91,6763 h60
  text "Copper" at 8130.5,6763 h60
  text "1.42mil" at 8990.27,6763 h60
  text "10" at 6311,6643 h60
  text "Dielectric 4" at 6720.91,6643 h60
  text "370HR" at 8130.5,6643 h60
  text "8.00mil" at 8990.27,6643 h60
  text "4.2" at 9640.1,6643 h60
  text "11" at 6311,6523 h60
  text "Layer 5 - PWR" at 6720.91,6523 h60
  text "Copper" at 8130.5,6523 h60
  text "1.40mil" at 8990.27,6523 h60
  text "12" at 6311,6403 h60
  text "Dielectric 5" at 6720.91,6403 h60
  text "370HR" at 8130.5,6403 h60
  text "12.60mil" at 8990.27,6403 h60
  text "4.2" at 9640.1,6403 h60
  text "13" at 6311,6283 h60
  text "Layer 6 - Bottom Layer" at 6720.91,6283 h60
  text "Copper" at 8130.5,6283 h60
  text "1.40mil" at 8990.27,6283 h60
  text "14" at 6311,6163 h60
  text "Bottom Solder" at 6720.91,6163 h60
  text "Solder Resist" at 8130.5,6163 h60
  text "0.40mil" at 8990.27,6163 h60
  text "3.5" at 9640.1,6163 h60
  text "15" at 6311,6043 h60
  text "Bottom Overlay" at 6720.91,6043 h60
  text ".Layer_Name" at 577,-858.49 h60
M13 Component Bodies Top:
  text ".Layer_Name" at 577,-858.49 h60
M14 Component Bodies Bottom:
  text ".Layer_Name" at 577,-858.49 h60
M15 Courtyards Top:
  text ".Layer_Name" at 577,-858.49 h60
M16 Courtyards Bottom:
  text ".Layer_Name" at 577,-858.49 h60
Drill Drawing:
  circle w10: c1588.72,584.68 r16.58
  circle w10: c1588.72,584.68 r27.63
  lines w10: 1561.09,432.74 1616.34,432.74 1616.34,487.99 1561.09,487.99 1561.09,432.74 ; 1561.09,695.19 1574.9,695.19 1588.72,681.38 1602.53,695.19 1616.34,695.19 1602.53,709 1616.34,722.82 1602.53,722.82 1588.72,736.63 1574.9,722.82 1561.09,722.82 1574.9,709 1561.09,695.19 ; 1561.09,819.51 1574.9,819.51 1574.9,805.7 1602.53,805.7 1602.53,819.51 1616.34,819.51 1616.34,847.14 1602.53,847.14 1602.53,860.95 1574.9,860.95 1574.9,847.14 1561.09,847.14 1561.09,819.51 ; 1561.09,930.02 1588.72,943.83 1616.34,930.02 1602.53,957.64 1616.34,985.27 1588.72,971.46 1561.09,985.27 1574.9,957.64 1561.09,930.02 ; 1561.09,1109.59 1616.34,1109.59 1588.72,1054.34 1561.09,1109.59 ; 1561.09,1206.28 1588.72,1178.66 1616.34,1206.28 1588.72,1233.91 1561.09,1206.28 ; 1572.14,443.79 1605.29,443.79 1605.29,476.94 1572.14,476.94 1572.14,443.79 ; 1572.14,700.71 1580.43,700.71 1588.72,692.43 1597.01,700.71 1605.29,700.71 1597.01,709 1605.29,717.29 1597.01,717.29 1588.72,725.58 1580.43,717.29 1572.14,717.29 1580.43,709 1572.14,700.71 ; 1572.14,825.03 1580.43,825.03 1580.43,816.75 1597.01,816.75 1597.01,825.03 1605.29,825.03 1605.29,841.61 1597.01,841.61 1597.01,849.9 1580.43,849.9 1580.43,841.61 1572.14,841.61 1572.14,825.03 ; 1572.14,941.07 1588.72,949.35 1605.29,941.07 1597.01,957.64 1605.29,974.22 1588.72,965.93 1572.14,974.22 1580.43,957.64 1572.14,941.07 ; 1572.14,1098.54 1605.29,1098.54 1588.72,1065.39 1572.14,1098.54
  lines w12: 1511,395.44 3489.02,395.44 ; 1511,1265.68 3489.02,1265.68 ; 1848.86,271.12 1848.86,1390 ; 2180.86,271.12 2180.86,1390 ; 2817.43,271.12 2817.43,1390 ; 3076.57,271.12 3076.57,1390 ; 1511,271.12 3489.02,271.12 3489.02,1390 1511,1390 1511,271.12
  text "Symbol" at 1585.59,1302.98 h72
  text "Quantity" at 1886.16,1302.98 h72
  text "Finished Hole Size" at 2218.16,1302.98 h72
  text "Plated" at 2854.72,1302.98 h72
  text "Hole Type" at 3113.86,1302.98 h72
  text "2" at 1886.16,1178.66 h60
  text "62.99mil (1.600mm)" at 2218.16,1178.66 h60
  text "NPTH" at 2854.72,1178.66 h60
  text "Round" at 3113.86,1178.66 h60
  text "1" at 1886.16,1054.34 h60
  text "280.00mil (7.112mm)" at 2218.16,1054.34 h60
  text "NPTH" at 2854.72,1054.34 h60
  text "Round" at 3113.86,1054.34 h60
  text "46" at 1886.16,930.02 h60
  text "6.00mil (0.152mm)" at 2218.16,930.02 h60
  text "PTH" at 2854.72,930.02 h60
  text "Round" at 3113.86,930.02 h60
  text "7" at 1886.16,805.7 h60
  text "7.87mil (0.200mm)" at 2218.16,805.7 h60
  text "PTH" at 2854.72,805.7 h60
  text "Round" at 3113.86,805.7 h60
  text "59" at 1886.16,681.38 h60
  text "10.00mil (0.254mm)" at 2218.16,681.38 h60
  text "PTH" at 2854.72,681.38 h60
  text "Round" at 3113.86,681.38 h60
  text "1" at 1886.16,557.06 h60
  text "35.43mil (0.900mm)" at 2218.16,557.06 h60
  text "PTH" at 2854.72,557.06 h60
  text "Round" at 3113.86,557.06 h60
  text "4" at 1886.16,432.74 h60
  text "55.12mil (1.400mm)" at 2218.16,432.74 h60
  text "PTH" at 2854.72,432.74 h60
  text "Round" at 3113.86,432.74 h60
  text "120 Total" at 1886.16,308.42 h60
  text ".Layer_Name" at 577,-858.49 h60
Mechanical 17:
  circle w10: c530,400 r236.22
  circle w10: c530,400 r240.16
  lines w10: 175.67,305.51 140.24,305.51 cw(c140.24,400) 140.24,494.49 175.67,494.49 ; 884.33,305.51 921.71,305.51 ccw(c921.71,400) 921.71,494.49 884.33,494.49 ; 175.67,45.67 175.67,754.33 884.33,754.33 884.33,45.67 175.67,45.67 ; 215.04,85.04 844.96,85.04 844.96,714.96 215.04,714.96 215.04,85.04

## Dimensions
132.36,2.36 to 927.64,2.36 on M2 Board Dimensions
132.36,797.64 to 132.36,2.36 on M2 Board Dimensions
